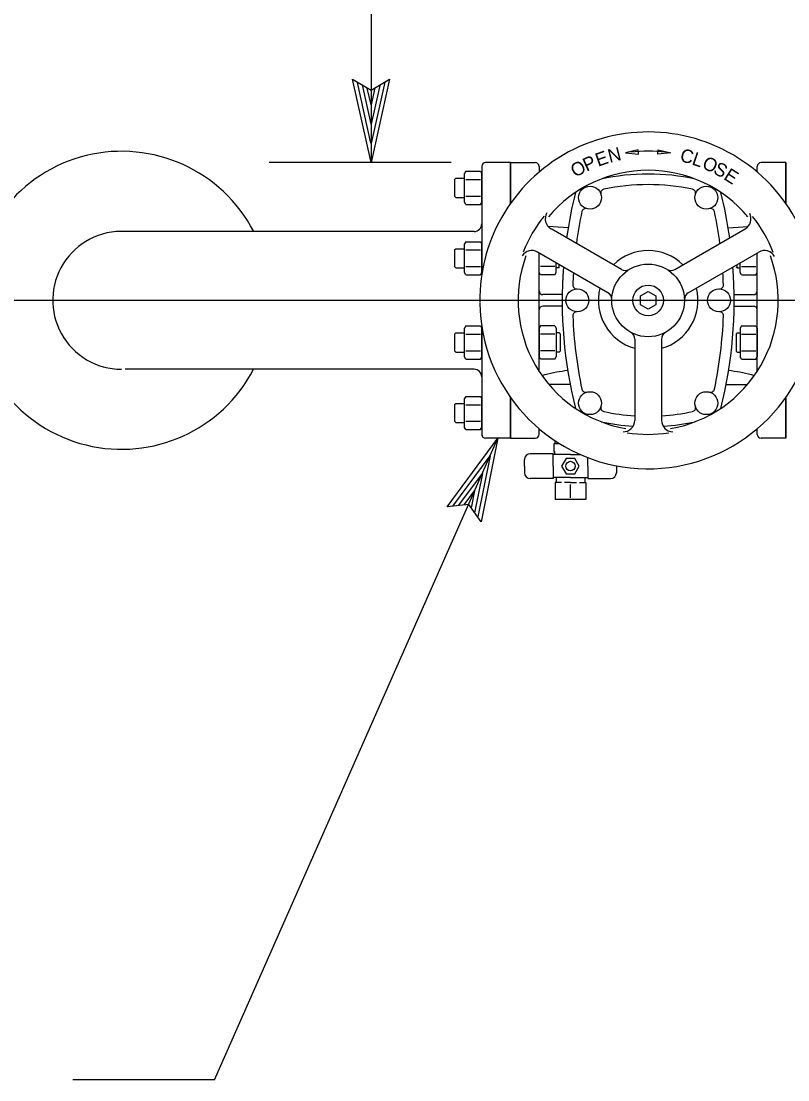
# Model space of a CAD drawing. Extents: x 6710407 to 6714861, y 1868090 to 1871317.
# Drawn here: x 6713785.8 to 6713841, y 1869917.9 to 1869994.1 of the extents above; entities that cross this region are included whole.
import ezdxf

# ---------------------------------------------------------------- set-up
doc = ezdxf.new("R2010")
doc.units = 0
doc.layers.add('Nongeo Data(60)', color=7, linetype='Continuous')

msp = doc.modelspace()

# ---------------------------------------------------------------- linework, layer by layer
at = {"layer": 'Nongeo Data(60)'}
for p, q in [((6713810.983, 1870034.779), (6713810.983, 1869983.89)), ((6713810.983, 1869983.89), (6713809.653, 1869989.89)), ((6713809.653, 1869989.89), (6713809.653, 1869989.89)), ((6713809.653, 1869989.89), (6713810.983, 1869989.09)), ((6713810.98, 1869985.281), (6713810.012, 1869989.655)), ((6713810.985, 1869986.652), (6713810.359, 1869989.477)), ((6713810.983, 1869989.09), (6713812.323, 1869989.89)), ((6713812.323, 1869989.89), (6713810.983, 1869983.89)), ((6713811.967, 1869989.673), (6713810.984, 1869985.269)), ((6713811.608, 1869989.439), (6713810.985, 1869986.652)), ((6713812.323, 1869989.89), (6713812.323, 1869989.89)), ((6713810.986, 1869988.034), (6713810.718, 1869989.243)), ((6713811.261, 1869989.263), (6713810.986, 1869988.034)), ((6713816.748, 1869983.89), (6713803.66, 1869983.89)), ((6713810.983, 1869983.89), (6713810.983, 1869983.89)), ((6713817.805, 1869983.268), (6713817.713, 1869983.108)), ((6713817.805, 1869983.268), (6713818.854, 1869983.268)), ((6713818.854, 1869983.268), (6713818.946, 1869983.108)), ((6713818.946, 1869983.614), (6713818.946, 1869975.799)), ((6713821.011, 1869983.89), (6713819.222, 1869983.89)), ((6713821.011, 1869983.89), (6713822.801, 1869983.89)), ((6713821.011, 1869980.943), (6713821.011, 1869983.89)), ((6713821.011, 1869983.89), (6713821.011, 1869980.943)), ((6713821.528, 1869983.891), (6713822.801, 1869983.891)), ((6713823.076, 1869983.614), (6713823.076, 1869983.207)), ((6713823.076, 1869983.268), (6713823.148, 1869983.268)), ((6713838.77, 1869983.207), (6713838.77, 1869983.614)), ((6713840.835, 1869983.89), (6713839.045, 1869983.89)), ((6713840.835, 1869980.943), (6713840.835, 1869983.89)), ((6713840.835, 1869983.89), (6713840.835, 1869980.943)), ((6713840.835, 1869983.89), (6713840.835, 1869980.943)), ((6713817.02, 1869982.698), (6713817.086, 1869982.764)), ((6713817.02, 1869981.453), (6713817.02, 1869982.698)), ((6713817.086, 1869982.764), (6713817.713, 1869982.764)), ((6713817.713, 1869981.043), (6713817.713, 1869983.108)), ((6713817.808, 1869982.672), (6713818.852, 1869982.672)), ((6713818.946, 1869981.043), (6713818.946, 1869983.108)), ((6713817.02, 1869981.453), (6713817.086, 1869981.387)), ((6713817.086, 1869981.387), (6713817.713, 1869981.387)), ((6713817.805, 1869980.883), (6713817.713, 1869981.043)), ((6713817.808, 1869981.48), (6713818.852, 1869981.48)), ((6713818.854, 1869980.883), (6713818.946, 1869981.043)), ((6713817.805, 1869980.883), (6713818.854, 1869980.883)), ((6713818.396, 1869978.934), (6713793.305, 1869978.934)), ((6713825.164, 1869979.201), (6713823.721, 1869979.302)), ((6713828.997, 1869976.203), (6713823.934, 1869979.126)), ((6713832.849, 1869976.203), (6713837.912, 1869979.126)), ((6713836.682, 1869979.201), (6713838.125, 1869979.302)), ((6713817.805, 1869978.202), (6713817.713, 1869978.042)), ((6713817.713, 1869975.977), (6713817.713, 1869978.042)), ((6713817.805, 1869978.202), (6713818.854, 1869978.202)), ((6713818.854, 1869978.202), (6713818.946, 1869978.042)), ((6713818.946, 1869975.977), (6713818.946, 1869978.042)), ((6713817.02, 1869977.632), (6713817.086, 1869977.698)), ((6713817.02, 1869976.387), (6713817.02, 1869977.632)), ((6713817.086, 1869977.698), (6713817.713, 1869977.698)), ((6713817.808, 1869977.606), (6713818.852, 1869977.606)), ((6713828.033, 1869974.534), (6713822.97, 1869977.457)), ((6713823.076, 1869968.873), (6713823.076, 1869977.396)), ((6713823.076, 1869975.977), (6713823.076, 1869977.396)), ((6713833.813, 1869974.534), (6713838.876, 1869977.457)), ((6713838.77, 1869968.873), (6713838.77, 1869977.396)), ((6713838.77, 1869975.977), (6713838.77, 1869977.396)), ((6713817.808, 1869976.414), (6713818.852, 1869976.414)), ((6713824.215, 1869976.413), (6713823.171, 1869976.413)), ((6713824.31, 1869975.977), (6713824.31, 1869976.683)), ((6713824.519, 1869976.321), (6713824.519, 1869976.563)), ((6713837.327, 1869976.321), (6713837.327, 1869976.563)), ((6713837.536, 1869975.977), (6713837.536, 1869976.683)), ((6713837.631, 1869976.413), (6713838.675, 1869976.413)), ((6713817.02, 1869976.387), (6713817.086, 1869976.321)), ((6713817.086, 1869976.321), (6713817.713, 1869976.321)), ((6713817.805, 1869975.817), (6713817.713, 1869975.977)), ((6713817.805, 1869975.817), (6713818.854, 1869975.817)), ((6713818.854, 1869975.817), (6713818.946, 1869975.977)), ((6713823.169, 1869975.817), (6713823.076, 1869975.977)), ((6713824.217, 1869975.817), (6713823.169, 1869975.817)), ((6713824.217, 1869975.817), (6713824.31, 1869975.977)), ((6713824.519, 1869976.321), (6713824.31, 1869976.321)), ((6713837.261, 1869976.387), (6713837.327, 1869976.321)), ((6713837.327, 1869976.321), (6713837.536, 1869976.321)), ((6713837.629, 1869975.817), (6713837.536, 1869975.977)), ((6713837.629, 1869975.817), (6713838.677, 1869975.817)), ((6713838.677, 1869975.817), (6713838.77, 1869975.977)), ((6713824.731, 1869974.391), (6713823.352, 1869974.391)), ((6713837.115, 1869974.391), (6713838.494, 1869974.391)), ((6713748.2, 1869973.985), (6713995.625, 1869973.985)), ((6713824.731, 1869973.565), (6713823.352, 1869973.565)), ((6713837.115, 1869973.565), (6713838.494, 1869973.565)), ((6713817.805, 1869972.139), (6713817.713, 1869971.979)), ((6713817.713, 1869969.914), (6713817.713, 1869971.979)), ((6713817.805, 1869972.139), (6713818.854, 1869972.139)), ((6713818.854, 1869972.139), (6713818.946, 1869971.979)), ((6713818.946, 1869972.157), (6713818.946, 1869964.342)), ((6713818.946, 1869969.914), (6713818.946, 1869971.979)), ((6713823.169, 1869972.139), (6713823.076, 1869971.979)), ((6713823.076, 1869971.979), (6713823.076, 1869969.914)), ((6713824.217, 1869972.139), (6713823.169, 1869972.139)), ((6713824.217, 1869972.139), (6713824.31, 1869971.979)), ((6713824.31, 1869971.979), (6713824.31, 1869969.914)), ((6713837.629, 1869972.139), (6713837.536, 1869971.979)), ((6713837.536, 1869971.979), (6713837.536, 1869969.914)), ((6713837.629, 1869972.139), (6713838.677, 1869972.139)), ((6713838.677, 1869972.139), (6713838.77, 1869971.979)), ((6713838.77, 1869971.979), (6713838.77, 1869969.914)), ((6713817.02, 1869971.569), (6713817.086, 1869971.635)), ((6713817.02, 1869970.324), (6713817.02, 1869971.569)), ((6713817.086, 1869971.635), (6713817.713, 1869971.635)), ((6713817.808, 1869971.542), (6713818.852, 1869971.542)), ((6713824.215, 1869971.542), (6713823.171, 1869971.542)), ((6713824.519, 1869971.635), (6713824.31, 1869971.635)), ((6713824.585, 1869971.569), (6713824.519, 1869971.635)), ((6713824.585, 1869971.569), (6713824.585, 1869970.324)), ((6713829.959, 1869971.197), (6713829.959, 1869965.351)), ((6713831.887, 1869971.197), (6713831.887, 1869965.351)), ((6713837.261, 1869971.569), (6713837.327, 1869971.635)), ((6713837.261, 1869971.569), (6713837.261, 1869970.324)), ((6713837.327, 1869971.635), (6713837.536, 1869971.635)), ((6713837.631, 1869971.542), (6713838.675, 1869971.542)), ((6713817.02, 1869970.324), (6713817.086, 1869970.258)), ((6713817.808, 1869970.35), (6713818.852, 1869970.35)), ((6713824.215, 1869970.35), (6713823.171, 1869970.35)), ((6713824.585, 1869970.324), (6713824.519, 1869970.258)), ((6713837.261, 1869970.324), (6713837.327, 1869970.258)), ((6713837.631, 1869970.35), (6713838.675, 1869970.35)), ((6713817.086, 1869970.258), (6713817.713, 1869970.258)), ((6713817.805, 1869969.754), (6713817.713, 1869969.914)), ((6713817.805, 1869969.754), (6713818.854, 1869969.754)), ((6713818.854, 1869969.754), (6713818.946, 1869969.914)), ((6713823.169, 1869969.754), (6713823.076, 1869969.914)), ((6713824.217, 1869969.754), (6713823.169, 1869969.754)), ((6713824.217, 1869969.754), (6713824.31, 1869969.914)), ((6713824.519, 1869970.258), (6713824.31, 1869970.258)), ((6713837.327, 1869970.258), (6713837.536, 1869970.258)), ((6713837.629, 1869969.754), (6713837.536, 1869969.914)), ((6713837.629, 1869969.754), (6713838.677, 1869969.754)), ((6713838.677, 1869969.754), (6713838.77, 1869969.914)), ((6713818.396, 1869969.022), (6713793.305, 1869969.022)), ((6713825.316, 1869967.921), (6713823.786, 1869967.921)), ((6713836.53, 1869967.921), (6713838.06, 1869967.921)), ((6713817.02, 1869966.503), (6713817.086, 1869966.569)), ((6713817.02, 1869965.258), (6713817.02, 1869966.503)), ((6713817.086, 1869966.569), (6713817.713, 1869966.569)), ((6713817.805, 1869967.072), (6713817.713, 1869966.913)), ((6713817.713, 1869964.848), (6713817.713, 1869966.913)), ((6713817.805, 1869967.072), (6713818.854, 1869967.072)), ((6713818.854, 1869967.072), (6713818.946, 1869966.913)), ((6713818.946, 1869964.848), (6713818.946, 1869966.913)), ((6713821.011, 1869967.013), (6713821.011, 1869964.066)), ((6713821.011, 1869964.066), (6713821.011, 1869967.013)), ((6713840.835, 1869964.066), (6713840.835, 1869967.013)), ((6713840.835, 1869967.013), (6713840.835, 1869964.066)), ((6713840.835, 1869967.013), (6713840.835, 1869964.066)), ((6713817.808, 1869966.476), (6713818.852, 1869966.476)), ((6713817.02, 1869965.258), (6713817.086, 1869965.192)), ((6713817.086, 1869965.192), (6713817.713, 1869965.192)), ((6713817.808, 1869965.284), (6713818.852, 1869965.284)), ((6713817.805, 1869964.688), (6713817.713, 1869964.848)), ((6713817.805, 1869964.688), (6713818.854, 1869964.688)), ((6713818.854, 1869964.688), (6713818.946, 1869964.848)), ((6713823.076, 1869964.342), (6713823.076, 1869964.749)), ((6713823.076, 1869964.688), (6713823.148, 1869964.688)), ((6713838.77, 1869964.342), (6713838.77, 1869964.749)), ((6713799.734, 1869917.919), (6713820.117, 1869964.066)), ((6713816.467, 1869959.119), (6713820.117, 1869964.066)), ((6713820.117, 1869964.066), (6713818.909, 1869958.04)), ((6713821.011, 1869964.066), (6713819.222, 1869964.066)), ((6713820.117, 1869964.066), (6713820.117, 1869964.066)), ((6713821.011, 1869964.066), (6713822.801, 1869964.066)), ((6713824.131, 1869963.664), (6713824.131, 1869963.112)), ((6713824.569, 1869963.664), (6713824.131, 1869963.664)), ((6713824.231, 1869963.664), (6713824.231, 1869963.88)), ((6713840.835, 1869964.066), (6713839.045, 1869964.066)), ((6713816.88, 1869959.174), (6713819.559, 1869962.804)), ((6713819.558, 1869962.793), (6713818.675, 1869958.4)), ((6713824.093, 1869962.954), (6713822.441, 1869962.954)), ((6713824.093, 1869962.062), (6713824.093, 1869962.954)), ((6713825.332, 1869962.888), (6713824.093, 1869962.888)), ((6713824.231, 1869963.063), (6713824.165, 1869963.063)), ((6713824.183, 1869963.026), (6713824.183, 1869962.888)), ((6713825.332, 1869962.888), (6713826.049, 1869962.888)), ((6713822.028, 1869962.062), (6713822.028, 1869962.541)), ((6713822.028, 1869962.062), (6713822.028, 1869961.583)), ((6713824.093, 1869962.062), (6713824.093, 1869961.17)), ((6713826.571, 1869962.062), (6713826.571, 1869962.672)), ((6713826.571, 1869962.062), (6713826.571, 1869961.17)), ((6713828.636, 1869962.062), (6713828.636, 1869962.082)), ((6713828.636, 1869962.062), (6713828.636, 1869961.583)), ((6713817.303, 1869959.242), (6713818.998, 1869961.54)), ((6713818.998, 1869961.54), (6713818.43, 1869958.703)), ((6713825.332, 1869961.236), (6713824.093, 1869961.236)), ((6713824.3, 1869961.226), (6713824.3, 1869960.911)), ((6713825.332, 1869961.236), (6713826.571, 1869961.236)), ((6713826.365, 1869961.226), (6713826.365, 1869960.911)), ((6713824.093, 1869961.17), (6713822.441, 1869961.17)), ((6713824.682, 1869960.876), (6713824.231, 1869960.876)), ((6713824.231, 1869960.876), (6713824.231, 1869959.659)), ((6713825.332, 1869960.876), (6713824.906, 1869960.876)), ((6713825.332, 1869960.876), (6713825.758, 1869960.876)), ((6713825.332, 1869959.787), (6713825.332, 1869960.748)), ((6713825.983, 1869960.876), (6713826.434, 1869960.876)), ((6713826.434, 1869960.876), (6713826.434, 1869959.659)), ((6713826.571, 1869961.17), (6713828.223, 1869961.17)), ((6713817.691, 1869959.263), (6713818.439, 1869960.277)), ((6713818.439, 1869960.277), (6713818.196, 1869959.063)), ((6713825.332, 1869959.659), (6713824.231, 1869959.659)), ((6713826.434, 1869959.659), (6713825.332, 1869959.659)), ((6713818.016, 1869959.31), (6713816.467, 1869959.119)), ((6713816.467, 1869959.119), (6713816.467, 1869959.119)), ((6713818.909, 1869958.041), (6713818.016, 1869959.31)), ((6713818.909, 1869958.041), (6713818.909, 1869958.041)), ((6713799.734, 1869917.919), (6713789.527, 1869917.919))]:
    msp.add_line(p, q, dxfattribs=at)
for points in [[(6713830.234, 1869984.507), (6713830.211, 1869984.816), (6713829.296, 1869984.592)], [(6713831.612, 1869984.507), (6713831.635, 1869984.816), (6713832.55, 1869984.592)], [(6713830.372, 1869974.296), (6713830.923, 1869974.614), (6713831.474, 1869974.296), (6713831.474, 1869973.66), (6713830.923, 1869973.342), (6713830.372, 1869973.66)], [(6713825.014, 1869962.612), (6713824.696, 1869962.062), (6713825.014, 1869961.511), (6713825.65, 1869961.511), (6713825.968, 1869962.062), (6713825.65, 1869962.612)]]:
    msp.add_lwpolyline(points, close=True, dxfattribs=at)
for centre, radius in [((6713826.741, 1869981.368), 0.826), ((6713835.105, 1869981.368), 0.826), ((6713830.923, 1869973.978), 2.616), ((6713830.923, 1869973.978), 1.101), ((6713825.83, 1869973.978), 0.826), ((6713836.016, 1869973.978), 0.826), ((6713826.741, 1869966.588), 0.826), ((6713835.105, 1869966.588), 0.826), ((6713825.332, 1869962.062), 0.344)]:
    msp.add_circle(centre, radius, dxfattribs=at)
for centre, radius, start, end in [((6713830.923, 1869973.978), 12.114, 346.86344, 180.73474), ((6713793.038, 1869973.985), 10.716, 27.50414, 332.42888), ((6713830.923, 1869973.978), 10.738, 83.28613, 96.71387), ((6713819.222, 1869983.614), 0.275, 90, 180), ((6713821.528, 1869984.166), 0.275, 258.23171, 270), ((6713822.801, 1869983.614), 0.275, 0, 90), ((6713830.923, 1869973.978), 9.361, 39.89685, 140.10315), ((6713839.045, 1869983.614), 0.275, 90, 180), ((6713830.923, 1869966.946), 16.118, 77.84886, 102.15114), ((6713856.253, 1869973.978), 31.524, 165.73336, 171.78835), ((6713827.79, 1869981.702), 0.275, 101.98605, 197.65954), ((6713830.923, 1869966.946), 15.361, 90, 101.98605), ((6713830.923, 1869966.946), 15.361, 78.01395, 90), ((6713834.056, 1869981.702), 0.275, 342.34046, 78.01395), ((6713805.593, 1869973.978), 31.524, 8.21165, 14.26664), ((6713824.347, 1869979.841), 0.826, 148.68649, 240), ((6713856.253, 1869973.978), 30.767, 168.00918, 172.35308), ((6713826.426, 1869980.313), 0.275, 73.39256, 168.00918), ((6713835.42, 1869980.313), 0.275, 11.99082, 106.60744), ((6713805.593, 1869973.978), 30.767, 7.64692, 11.99082), ((6713837.499, 1869979.841), 0.826, 300, 28.20849), ((6713818.396, 1869979.484), 0.551, 270, 0), ((6713830.923, 1869973.978), 9.636, 140.95405, 158.82668), ((6713830.923, 1869973.978), 9.636, 20.95405, 38.82668), ((6713793.038, 1869973.985), 4.956, 86.91279, 269.99938), ((6713830.923, 1869973.978), 9.361, 159.89685, 260.10315), ((6713822.557, 1869976.741), 0.826, 60, 148.20849), ((6713830.923, 1869973.978), 3.579, 45.6185, 134.3815), ((6713830.923, 1869973.978), 9.361, 279.89685, 20.10315), ((6713839.289, 1869976.741), 0.826, 28.68649, 120), ((6713856.253, 1869973.978), 31.524, 175.61453, 194.26664), ((6713856.253, 1869973.978), 30.767, 176.29245, 177.93223), ((6713829.272, 1869976.68), 0.551, 240, 301.42812), ((6713832.574, 1869976.68), 0.551, 238.57188, 300), ((6713805.593, 1869973.978), 31.524, 345.73336, 4.38547), ((6713805.593, 1869973.978), 30.767, 2.06778, 3.70755), ((6713825.781, 1869975.078), 0.275, 177.93223, 272.54885), ((6713836.065, 1869975.078), 0.275, 267.45115, 2.06778), ((6713823.352, 1869974.666), 0.275, 180, 270), ((6713830.923, 1869973.978), 3.579, 165.6185, 254.3815), ((6713827.758, 1869974.057), 0.551, 358.57188, 60), ((6713830.923, 1869973.978), 3.579, 285.6185, 14.3815), ((6713834.088, 1869974.057), 0.551, 120, 181.42812), ((6713838.494, 1869974.666), 0.275, 270, 0), ((6713830.923, 1869973.978), 12.114, 180.91058, 346.86344), ((6713823.352, 1869973.29), 0.275, 90, 180), ((6713838.494, 1869973.29), 0.275, 0, 90), ((6713825.781, 1869972.878), 0.275, 87.45115, 182.06778), ((6713856.253, 1869973.978), 30.767, 182.06778, 191.99082), ((6713805.593, 1869973.978), 30.767, 348.00918, 357.93223), ((6713836.065, 1869972.878), 0.275, 357.93223, 92.54885), ((6713829.409, 1869971.197), 0.551, 0, 61.42812), ((6713832.437, 1869971.197), 0.551, 118.57188, 180), ((6713818.396, 1869968.472), 0.551, 0, 90), ((6713826.215, 1869958.231), 10.748, 95.76035, 104.57611), ((6713835.631, 1869958.231), 10.748, 75.42389, 84.23965), ((6713823.792, 1869967.729), 0.948, 107.31382, 121.04157), ((6713838.054, 1869967.729), 0.948, 58.95843, 72.68618), ((6713826.426, 1869967.643), 0.275, 191.99082, 286.60744), ((6713835.42, 1869967.643), 0.275, 253.39256, 348.00918), ((6713827.79, 1869966.254), 0.275, 162.34046, 258.01395), ((6713830.923, 1869981.01), 15.361, 258.01395, 266.40328), ((6713830.923, 1869981.01), 15.361, 273.59672, 281.98605), ((6713834.056, 1869966.254), 0.275, 281.98605, 17.65954), ((6713830.923, 1869981.01), 16.118, 257.84886, 266.06847), ((6713829.133, 1869965.351), 0.826, 268.68649, 0), ((6713832.713, 1869965.351), 0.826, 180, 268.20849), ((6713830.923, 1869981.01), 16.118, 273.93153, 282.15114), ((6713819.222, 1869964.342), 0.275, 180, 230.92844), ((6713819.222, 1869964.342), 0.275, 180, 270), ((6713822.801, 1869964.342), 0.275, 270, 0), ((6713830.923, 1869973.978), 9.636, 260.95405, 278.82668), ((6713839.045, 1869964.342), 0.275, 180, 270), ((6713822.441, 1869962.541), 0.413, 90, 180), ((6713824.179, 1869963.112), 0.0481, 180, 242.72039), ((6713824.135, 1869963.026), 0.0481, 0, 62.72039), ((6713822.441, 1869961.583), 0.413, 180, 270), ((6713826.399, 1869961.226), 0.0344, 164.17334, 180), ((6713828.223, 1869961.583), 0.413, 270, 0), ((6713824.265, 1869960.911), 0.0344, 270, 0), ((6713826.399, 1869960.911), 0.0344, 180, 270)]:
    msp.add_arc(centre, radius, start, end, dxfattribs=at)

# ---------------------------------------------------------------- texts
for s, rotation, p in [('N', 14.33908, (6713828.16, 1869983.866)), ('C', 346.07317, (6713833.157, 1869983.996)), ('P', 24.33908, (6713826.491, 1869983.226)), ('E', 19.33908, (6713827.325, 1869983.584)), ('L', 341.38567, (6713834.013, 1869983.768)), ('O', 336.69817, (6713834.739, 1869983.508)), ('O', 29.33908, (6713825.678, 1869982.792)), ('S', 332.01067, (6713835.542, 1869983.15)), ('E', 327.32317, (6713836.289, 1869982.738))]:
    msp.add_text(s, height=0.964, rotation=rotation, dxfattribs=at).set_placement(p)

doc.saveas('drawing.dxf')
